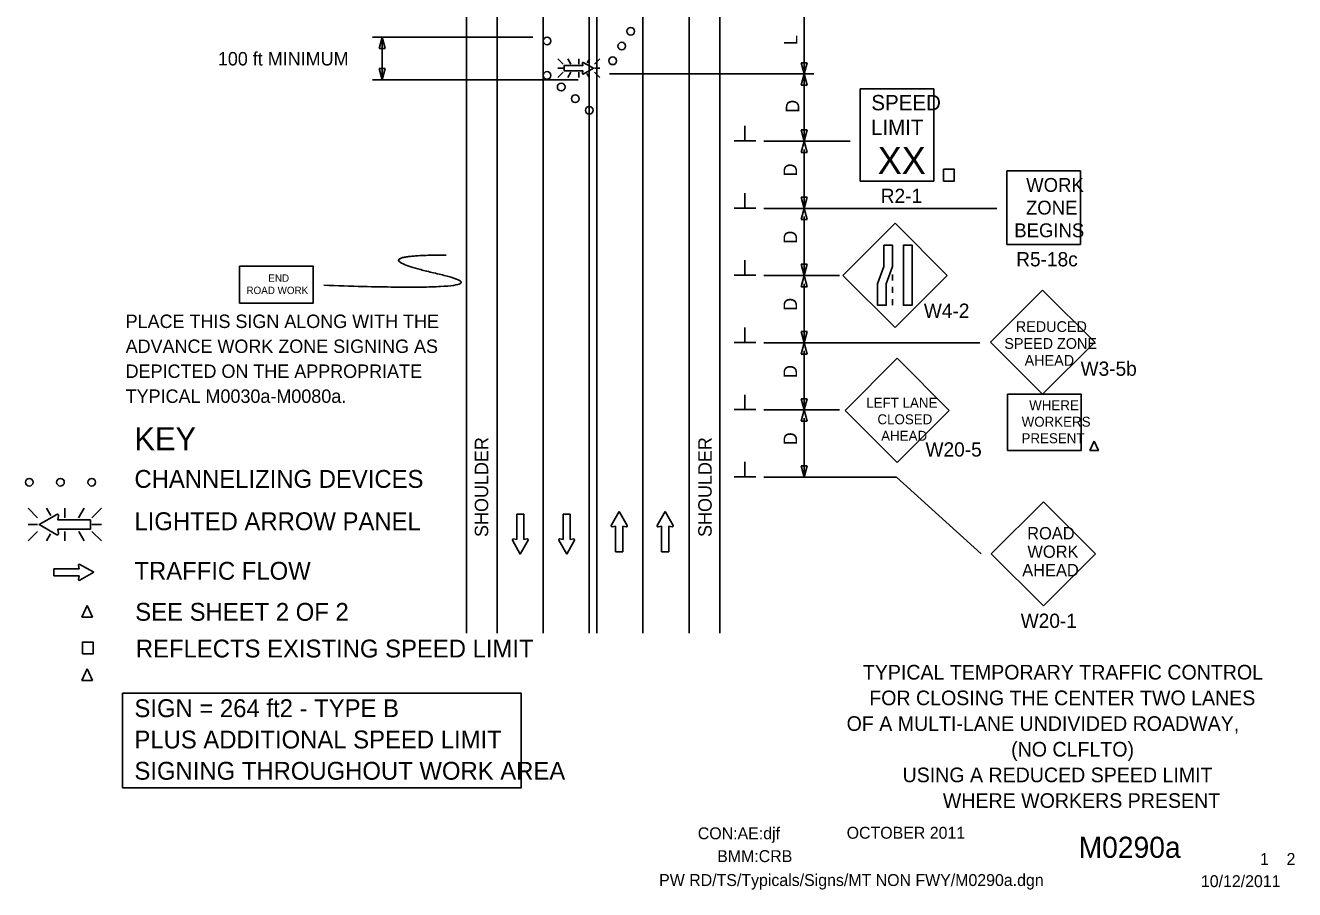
# Model space of a CAD drawing. Extents: x 16729 to 18475, y 5932 to 6920.
# Drawn here: x 16740 to 17402, y 5932 to 6382 of the extents above; entities that cross this region are included whole.
import ezdxf

# ---------------------------------------------------------------- set-up
doc = ezdxf.new("R2010")
doc.units = 0
for name, color, linetype in [('ALI_LEGAL_EX', 7, 'Continuous'), ('BORDER_SIGNAL_WO', 7, 'Continuous'), ('Level 44', 7, 'Continuous'), ('MT_SCRATCH_LEVEL_E', 7, 'Continuous'), ('PAVT_EDGE_EX', 7, 'Continuous'), ('TRAFFIC_SIGNS_PR', 7, 'Continuous'), ('TYPICAL_TEXT_DIMEN_EX', 7, 'Continuous'), ('TYPICAL_TEXT_DIMEN_PR', 7, 'Continuous')]:
    doc.layers.add(name, color=color, linetype=linetype)

msp = doc.modelspace()

# ---------------------------------------------------------------- linework, layer by layer
at = {"layer": 'ALI_LEGAL_EX'}
for p, q in [((17010.12, 6916.46), (17010.12, 6065.34)), ((17062.12, 6916.46), (17062.12, 6065.34))]:
    msp.add_line(p, q, dxfattribs=at)
for points in [[(17010.12, 6316.46), (17010.12, 6291.46)], [(17062.12, 6316.46), (17062.12, 6291.46)], [(17010.12, 6216.46), (17010.12, 6191.46)], [(17062.12, 6216.46), (17062.12, 6191.46)], [(17010.12, 6116.46), (17010.12, 6091.46)], [(17062.12, 6116.46), (17062.12, 6091.46)]]:
    msp.add_lwpolyline(points, dxfattribs=at)
at = {"layer": 'MT_SCRATCH_LEVEL_E'}
for p, q in [((17000.04, 6127.4), (16996.3, 6127.4)), ((16996.3, 6127.4), (16996.3, 6114.15)), ((17000.04, 6127.4), (16996.3, 6127.4)), ((16996.3, 6127.4), (16996.3, 6114.15)), ((17000.04, 6114.15), (17000.04, 6127.4)), ((17000.04, 6114.15), (17000.04, 6127.4)), ((17024.22, 6127.4), (17020.48, 6127.4)), ((17020.48, 6127.4), (17020.48, 6114.15)), ((17024.22, 6127.4), (17020.48, 6127.4)), ((17020.48, 6127.4), (17020.48, 6114.15)), ((17024.22, 6114.15), (17024.22, 6127.4)), ((17024.22, 6114.15), (17024.22, 6127.4)), ((17049.71, 6128.69), (17045.6, 6121.45)), ((17049.71, 6128.69), (17045.6, 6121.45)), ((17053.86, 6121.45), (17049.71, 6128.69)), ((17053.86, 6121.45), (17049.71, 6128.69)), ((17073.64, 6128.69), (17069.53, 6121.45)), ((17073.64, 6128.69), (17069.53, 6121.45)), ((17077.78, 6121.45), (17073.64, 6128.69)), ((17077.78, 6121.45), (17073.64, 6128.69)), ((17046.08, 6120.77), (17047.86, 6121.08)), ((17046.08, 6120.77), (17047.86, 6121.08)), ((17047.86, 6121.08), (17047.86, 6107.82)), ((17047.86, 6121.08), (17047.86, 6107.82)), ((17051.6, 6107.82), (17051.6, 6121.08)), ((17051.6, 6121.08), (17053.38, 6120.77)), ((17051.6, 6107.82), (17051.6, 6121.08)), ((17051.6, 6121.08), (17053.38, 6120.77)), ((17070.01, 6120.77), (17071.79, 6121.08)), ((17070.01, 6120.77), (17071.79, 6121.08)), ((17071.79, 6121.08), (17071.79, 6107.82)), ((17071.79, 6121.08), (17071.79, 6107.82)), ((17075.53, 6107.82), (17075.53, 6121.08)), ((17075.53, 6121.08), (17077.3, 6120.77)), ((17075.53, 6107.82), (17075.53, 6121.08)), ((17075.53, 6121.08), (17077.3, 6120.77)), ((16994.04, 6113.78), (16998.19, 6106.54)), ((16994.04, 6113.78), (16998.19, 6106.54)), ((16996.3, 6114.15), (16994.52, 6114.46)), ((16996.3, 6114.15), (16994.52, 6114.46)), ((16998.19, 6106.54), (17002.3, 6113.78)), ((16998.19, 6106.54), (17002.3, 6113.78)), ((17001.82, 6114.46), (17000.04, 6114.15)), ((17001.82, 6114.46), (17000.04, 6114.15)), ((17018.22, 6113.78), (17022.37, 6106.54)), ((17018.22, 6113.78), (17022.37, 6106.54)), ((17020.48, 6114.15), (17018.7, 6114.46)), ((17020.48, 6114.15), (17018.7, 6114.46)), ((17022.37, 6106.54), (17026.48, 6113.78)), ((17022.37, 6106.54), (17026.48, 6113.78)), ((17026, 6114.46), (17024.22, 6114.15)), ((17026, 6114.46), (17024.22, 6114.15)), ((17047.86, 6107.82), (17051.6, 6107.82)), ((17047.86, 6107.82), (17051.6, 6107.82)), ((17071.79, 6107.82), (17075.53, 6107.82)), ((17071.79, 6107.82), (17075.53, 6107.82)), ((16767.91, 6100.73), (16768.23, 6098.95)), ((16767.91, 6100.73), (16768.23, 6098.95)), ((16775.84, 6097.1), (16768.6, 6101.21)), ((16775.84, 6097.1), (16768.6, 6101.21)), ((16768.23, 6098.95), (16754.97, 6098.95)), ((16754.97, 6098.95), (16754.97, 6095.21)), ((16768.23, 6098.95), (16754.97, 6098.95)), ((16754.97, 6098.95), (16754.97, 6095.21)), ((16754.97, 6095.21), (16768.23, 6095.21)), ((16754.97, 6095.21), (16768.23, 6095.21)), ((16768.23, 6095.21), (16767.91, 6093.43)), ((16768.23, 6095.21), (16767.91, 6093.43)), ((16768.6, 6092.95), (16775.84, 6097.1)), ((16768.6, 6092.95), (16775.84, 6097.1))]:
    msp.add_line(p, q, dxfattribs=at)
for centre, start, end in [((17046.01, 6121.23), 150.42484, 279.96381), ((17046.01, 6121.23), 150.42484, 279.96381), ((17053.45, 6121.23), 260.03619, 29.77312), ((17053.45, 6121.23), 260.03619, 29.77312), ((17069.93, 6121.23), 150.42484, 279.96381), ((17069.93, 6121.23), 150.42484, 279.96381), ((17077.37, 6121.23), 260.03619, 29.77312), ((17077.37, 6121.23), 260.03619, 29.77312), ((16994.45, 6114), 80.03619, 209.77312), ((16994.45, 6114), 80.03619, 209.77312), ((17001.89, 6114), 330.42484, 99.96381), ((17001.89, 6114), 330.42484, 99.96381), ((17018.63, 6114), 80.03619, 209.77312), ((17018.63, 6114), 80.03619, 209.77312), ((17026.07, 6114), 330.42484, 99.96381), ((17026.07, 6114), 330.42484, 99.96381), ((16768.37, 6100.8), 60.42484, 189.96381), ((16768.37, 6100.8), 60.42484, 189.96381), ((16768.37, 6093.36), 170.03619, 299.77312), ((16768.37, 6093.36), 170.03619, 299.77312)]:
    msp.add_arc(centre, 0.463, start, end, dxfattribs=at)
at = {"layer": 'PAVT_EDGE_EX'}
for p, q in [((16970.12, 6916.46), (16970.12, 6065.34)), ((16986.12, 6916.46), (16986.12, 6065.34)), ((17086.12, 6916.46), (17086.12, 6065.34)), ((17102.12, 6916.46), (17102.12, 6065.34)), ((17034.12, 6439.88), (17034.12, 6065.34)), ((17038.12, 6439.88), (17038.12, 6065.34))]:
    msp.add_line(p, q, dxfattribs=at)
at = {"layer": 'TRAFFIC_SIGNS_PR'}
for p, q in [((17020.6, 6361.69), (17017.78, 6364.51)), ((17022.9, 6364.51), (17024.53, 6361.69)), ((17028.69, 6361.69), (17028.69, 6364.51)), ((17034.16, 6364.51), (17032.95, 6362.42)), ((17039.59, 6364.51), (17036.77, 6361.69)), ((17020.6, 6359.66), (17017.78, 6359.66)), ((17020.6, 6357.63), (17017.78, 6354.81)), ((17024.55, 6357.63), (17022.92, 6354.81)), ((17028.69, 6357.63), (17028.69, 6354.81)), ((17036.77, 6359.66), (17039.59, 6359.66)), ((17039.59, 6354.81), (17036.77, 6357.63)), ((17032.87, 6356.99), (17034.13, 6354.81)), ((17175.37, 6348.87), (17213.77, 6348.87)), ((17175.37, 6300.87), (17175.37, 6348.87)), ((17213.77, 6300.87), (17213.77, 6348.87)), ((17251.85, 6267.89), (17251.85, 6306.29)), ((17251.85, 6306.29), (17290.25, 6306.29)), ((17290.25, 6267.89), (17290.25, 6306.29)), ((17175.37, 6300.87), (17213.77, 6300.87)), ((17193.49, 6278.91), (17166.33, 6251.75)), ((17220.64, 6251.75), (17193.49, 6278.91)), ((17251.85, 6267.89), (17290.25, 6267.89)), ((17166.33, 6251.75), (17193.49, 6224.6)), ((17192.24, 6252.24), (17192.24, 6249.04)), ((17193.49, 6224.6), (17220.64, 6251.75)), ((17192.24, 6245.84), (17192.24, 6242.64)), ((17192.24, 6239.44), (17192.24, 6236.24)), ((17270.42, 6244.13), (17243.26, 6216.98)), ((17297.57, 6216.98), (17270.42, 6244.13)), ((17243.26, 6216.98), (17270.42, 6189.82)), ((17270.42, 6189.82), (17297.57, 6216.98)), ((17194.61, 6208.56), (17167.46, 6181.4)), ((17221.77, 6181.4), (17194.61, 6208.56)), ((17252.1, 6189.85), (17290.5, 6189.85)), ((17252.1, 6160.53), (17252.1, 6189.85)), ((17290.5, 6160.53), (17290.5, 6189.85)), ((17167.46, 6181.4), (17194.61, 6154.25)), ((17194.61, 6154.25), (17221.77, 6181.4)), ((17252.1, 6160.53), (17290.5, 6160.53)), ((17270.83, 6133.88), (17243.68, 6106.73)), ((17297.99, 6106.73), (17270.83, 6133.88)), ((16741.65, 6130.48), (16746.58, 6125.55)), ((16753.41, 6126.66), (16751.2, 6130.49)), ((16760.73, 6125.55), (16760.73, 6130.49)), ((16767.97, 6125.55), (16770.82, 6130.49)), ((16774.88, 6125.55), (16779.82, 6130.49)), ((16746.58, 6122), (16741.65, 6122)), ((16774.88, 6122), (16779.82, 6122)), ((16741.65, 6113.51), (16746.58, 6118.44)), ((16751.16, 6113.51), (16753.27, 6117.17)), ((16760.73, 6118.44), (16760.73, 6113.51)), ((16770.86, 6113.51), (16768.01, 6118.44)), ((16774.88, 6118.44), (16779.82, 6113.5)), ((17243.68, 6106.73), (17270.83, 6079.57)), ((17270.83, 6079.57), (17297.99, 6106.73))]:
    msp.add_line(p, q, dxfattribs=at)
for points in [[(17030.51, 6362.34), (17030.74, 6361.05), (17021.02, 6361.05), (17021.02, 6358.3), (17030.74, 6358.3), (17030.51, 6357)], [(17031.01, 6356.64), (17036.32, 6359.66), (17031.01, 6362.7)], [(17297.25, 6165.47), (17295.02, 6160.53)], [(17295.02, 6160.53), (17297.25, 6165.47)], [(17295.02, 6160.53), (17299.49, 6160.53)], [(17299.49, 6160.53), (17295.02, 6160.53)], [(17299.49, 6160.53), (17297.25, 6165.47)], [(17297.25, 6165.47), (17299.49, 6160.53)], [(16756.66, 6127.27), (16747.37, 6122), (16756.66, 6116.67)], [(16757.53, 6117.3), (16757.13, 6119.57), (16774.15, 6119.57), (16774.15, 6124.37), (16757.13, 6124.37), (16757.54, 6126.65)], [(16772.39, 6079.87), (16769.59, 6073.7)], [(16775.19, 6073.7), (16772.39, 6079.87)], [(16769.59, 6073.7), (16775.19, 6073.7)], [(16769.59, 6040.7), (16772.39, 6046.87)], [(16772.39, 6046.87), (16775.19, 6040.7)], [(16775.19, 6040.7), (16769.59, 6040.7)]]:
    msp.add_lwpolyline(points, dxfattribs=at)
for points in [[(17218.79, 6300.87), (17224.38, 6300.87), (17224.38, 6307.04), (17218.79, 6307.04)], [(17192.24, 6267.49), (17192.24, 6256.31), (17188.89, 6247.43), (17188.89, 6236.24), (17184.4, 6236.24), (17184.4, 6247.43), (17187.74, 6256.31), (17187.74, 6267.49)], [(17202.37, 6267.49), (17202.37, 6236.24), (17197.88, 6236.24), (17197.88, 6267.49)], [(16851.85, 6237.29), (16890.25, 6237.29), (16890.25, 6256.49), (16851.85, 6256.49)], [(16769.91, 6054.58), (16775.5, 6054.58), (16775.5, 6060.75), (16769.91, 6060.75)]]:
    msp.add_lwpolyline(points, close=True, dxfattribs=at)
for centre in [(17055.74, 6378.87), (17012.15, 6373.87), (17051.04, 6371.19), (17046.34, 6363.52), (17012.15, 6355.91), (17019.48, 6349.85), (17026.8, 6343.78), (17034.13, 6337.72), (16742.21, 6144.03), (16758.51, 6144.03), (16774.81, 6144.03)]:
    msp.add_circle(centre, 2, dxfattribs=at)
for centre, radius, start, end in [((17030.85, 6362.4), 0.341, 61.48329, 189.95933), ((17030.85, 6356.94), 0.341, 170.73078, 298.89165), ((16756.95, 6126.75), 0.598, 350.73078, 118.89165), ((16756.95, 6117.2), 0.597, 241.48329, 9.95933)]:
    msp.add_arc(centre, radius, start, end, dxfattribs=at)
msp.add_open_spline([(16959.57, 6262.32), (16912.34, 6262.32), (16997.36, 6242.97), (16895.79, 6246.61)], degree=2, dxfattribs=at)
at = {"layer": 'TYPICAL_TEXT_DIMEN_EX'}
msp.add_lwpolyline([(16790.87, 6034.08), (16998.68, 6034.08), (16998.68, 5984.89), (16790.87, 5984.89)], close=True, dxfattribs=at)
at = {"layer": 'TYPICAL_TEXT_DIMEN_PR'}
for p, q in [((17146.12, 6388.9), (17146.12, 6356.65)), ((16921.12, 6375.88), (17004.78, 6375.88)), ((16924.55, 6370.01), (16926.12, 6375.88)), ((16926.12, 6375.88), (16926.12, 6353.68)), ((16926.12, 6375.88), (16927.69, 6370.01)), ((16926.12, 6370.01), (16924.55, 6370.01)), ((16927.69, 6370.01), (16926.12, 6370.01)), ((16926.12, 6353.68), (16924.55, 6359.55)), ((16924.55, 6359.55), (16926.12, 6359.55)), ((16926.12, 6359.55), (16927.69, 6359.55)), ((16927.69, 6359.55), (16926.12, 6353.68)), ((17146.12, 6356.65), (17144.55, 6362.51)), ((17144.55, 6362.51), (17146.12, 6362.51)), ((17146.12, 6362.51), (17147.69, 6362.51)), ((17147.69, 6362.51), (17146.12, 6356.65)), ((16921.12, 6353.68), (17028.42, 6353.68)), ((17044.68, 6356.65), (17151.12, 6356.65)), ((17144.55, 6350.79), (17146.12, 6356.65)), ((17146.12, 6356.65), (17146.12, 6321.65)), ((17146.12, 6356.65), (17147.69, 6350.79)), ((17146.12, 6350.79), (17144.55, 6350.79)), ((17147.69, 6350.79), (17146.12, 6350.79)), ((17115.24, 6321.82), (17115.24, 6329.61)), ((17146.12, 6321.65), (17144.55, 6327.51)), ((17144.55, 6327.51), (17146.12, 6327.51)), ((17146.12, 6327.51), (17147.69, 6327.51)), ((17147.69, 6327.51), (17146.12, 6321.65)), ((17120.87, 6321.82), (17109.62, 6321.82)), ((17125.12, 6321.65), (17170.03, 6321.65)), ((17144.55, 6315.79), (17146.12, 6321.65)), ((17146.12, 6321.65), (17147.69, 6315.79)), ((17146.12, 6315.79), (17144.55, 6315.79)), ((17146.12, 6317.39), (17146.12, 6286.65)), ((17147.69, 6315.79), (17146.12, 6315.79)), ((17115.24, 6286.82), (17115.24, 6294.61)), ((17146.12, 6286.65), (17144.55, 6292.51)), ((17144.55, 6292.51), (17146.12, 6292.51)), ((17146.12, 6292.51), (17147.69, 6292.51)), ((17147.69, 6292.51), (17146.12, 6286.65)), ((17120.87, 6286.82), (17109.62, 6286.82)), ((17125.12, 6286.65), (17246.53, 6286.65)), ((17144.55, 6280.79), (17146.12, 6286.65)), ((17146.12, 6286.65), (17147.69, 6280.79)), ((17146.12, 6280.79), (17144.55, 6280.79)), ((17146.12, 6282.39), (17146.12, 6251.65)), ((17147.69, 6280.79), (17146.12, 6280.79)), ((17115.24, 6251.82), (17115.24, 6259.61)), ((17120.87, 6251.82), (17109.62, 6251.82)), ((17146.12, 6251.65), (17144.55, 6257.51)), ((17144.55, 6257.51), (17146.12, 6257.51)), ((17146.12, 6257.51), (17147.69, 6257.51)), ((17147.69, 6257.51), (17146.12, 6251.65)), ((17125.12, 6251.65), (17164.54, 6251.65)), ((17144.55, 6245.79), (17146.12, 6251.65)), ((17146.12, 6245.79), (17144.55, 6245.79)), ((17146.12, 6251.65), (17147.69, 6245.79)), ((17146.12, 6247.39), (17146.12, 6216.65)), ((17147.69, 6245.79), (17146.12, 6245.79)), ((17115.24, 6216.82), (17115.24, 6224.61)), ((17146.12, 6216.65), (17144.55, 6222.51)), ((17144.55, 6222.51), (17146.12, 6222.51)), ((17146.12, 6222.51), (17147.69, 6222.51)), ((17147.69, 6222.51), (17146.12, 6216.65)), ((17120.87, 6216.82), (17109.62, 6216.82)), ((17125.12, 6216.65), (17237.67, 6216.65)), ((17144.55, 6210.79), (17146.12, 6216.65)), ((17146.12, 6216.65), (17147.69, 6210.79)), ((17146.12, 6212.39), (17146.12, 6181.65)), ((17146.12, 6210.79), (17144.55, 6210.79)), ((17147.69, 6210.79), (17146.12, 6210.79)), ((17115.24, 6181.82), (17115.24, 6189.61)), ((17146.12, 6181.65), (17144.55, 6187.51)), ((17144.55, 6187.51), (17146.12, 6187.51)), ((17146.12, 6187.51), (17147.69, 6187.51)), ((17147.69, 6187.51), (17146.12, 6181.65)), ((17120.87, 6181.82), (17109.62, 6181.82)), ((17125.12, 6181.65), (17164.54, 6181.65)), ((17144.55, 6175.79), (17146.12, 6181.65)), ((17146.12, 6181.65), (17147.69, 6175.79)), ((17146.12, 6175.79), (17144.55, 6175.79)), ((17146.12, 6177.39), (17146.12, 6146.65)), ((17147.69, 6175.79), (17146.12, 6175.79)), ((17115.24, 6146.82), (17115.24, 6154.61)), ((17146.12, 6146.65), (17144.55, 6152.51)), ((17144.55, 6152.51), (17146.12, 6152.51)), ((17146.12, 6152.51), (17147.69, 6152.51)), ((17147.69, 6152.51), (17146.12, 6146.65)), ((17120.87, 6146.82), (17109.62, 6146.82)), ((17125.12, 6146.65), (17194.29, 6146.65)), ((17194.29, 6146.65), (17238.34, 6106.72))]:
    msp.add_line(p, q, dxfattribs=at)

# ---------------------------------------------------------------- texts
at = {"layer": 'BORDER_SIGNAL_WO'}
for s, height, p in [('CON:AE:djf', 6.2, (17090.69, 5958.06)), ('    OCTOBER 2011    ', 6.2, (17159.08, 5958.34)), ('    M0290a   ', 11, (17272.86, 5948.38)), ('BMM:CRB   ', 6.2, (17100.81, 5946.17)), (' 1    2 ', 6.2, (17381.45, 5944.7)), ('PW RD/TS/Typicals/Signs/MT NON FWY/M0290a.dgn    ', 6.2, (17070.55, 5933.71)), ('10/12/2011    ', 6.2, (17352.93, 5933.13))]:
    msp.add_text(s, height=height, dxfattribs=at).set_placement(p)
at = {"layer": 'Level 44'}
for s, p in [('TYPICAL TEMPORARY TRAFFIC CONTROL', (17176.72, 6041.25)), ('FOR CLOSING THE CENTER TWO LANES', (17180.06, 6027.88)), ('OF A MULTI-LANE UNDIVIDED ROADWAY, ', (17168.26, 6014.51)), ('(NO CLFLTO)', (17254.01, 6001.14)), ('USING A REDUCED SPEED LIMIT', (17197.43, 5987.77)), ('WHERE WORKERS PRESENT', (17218.43, 5974.4))]:
    msp.add_text(s, height=7.6293, dxfattribs=at).set_placement(p)
at = {"layer": 'TRAFFIC_SIGNS_PR'}
for s, height, p in [('SPEED', 8, (17181.14, 6337.73)), ('LIMIT', 8, (17180.98, 6324.93)), ('XX', 14.031, (17184.49, 6304.63)), ('WORK', 7.217, (17261.85, 6295.25)), ('R2-1', 7.44, (17186.05, 6289.43)), ('ZONE', 7.217, (17261.73, 6283.44)), ('BEGINS', 7.217, (17255.66, 6271.63)), ('R5-18c', 7.44, (17256.66, 6256.45)), ('END', 3.831, (16866.85, 6248.42)), ('ROAD WORK', 3.831, (16855.46, 6242.04)), ('W4-2', 7.44, (17208.51, 6229.62)), ('PLACE THIS SIGN ALONG WITH THE', 7, (16792.47, 6224.34)), ('REDUCED', 5.6, (17256.47, 6222.28)), ('SPEED ZONE', 5.6, (17250.47, 6213.48)), ('ADVANCE WORK ZONE SIGNING AS', 7, (16792.47, 6211.34)), ('DEPICTED ON THE APPROPRIATE', 7, (16792.47, 6198.34)), ('AHEAD', 5.6, (17261.03, 6204.68)), ('W3-5b', 7.44, (17290.21, 6199.44)), ('TYPICAL M0030a-M0080a.', 7, (16792.47, 6185.34)), ('LEFT LANE', 5.2, (17178.49, 6182.8)), ('WHERE', 5.2, (17263.41, 6181.53)), ('CLOSED', 5.2, (17184.33, 6174.2)), ('WORKERS', 5.2, (17259.49, 6172.93)), ('AHEAD', 5.2, (17186.27, 6165.6)), ('PRESENT', 5.2, (17259.42, 6164.33)), ('W20-5', 7.44, (17209.38, 6157.37)), ('ROAD', 6.4, (17262.37, 6114.26)), ('WORK', 6.4, (17262.48, 6104.66)), ('AHEAD', 6.4, (17259.79, 6095.06)), ('W20-1', 7.44, (17259, 6068.13))]:
    msp.add_text(s, height=height, dxfattribs=at).set_placement(p)
at = {"layer": 'TYPICAL_TEXT_DIMEN_EX'}
for s, height, p in [('KEY', 12, (16797.05, 6160.65)), ('CHANNELIZING DEVICES', 9.3, (16797.05, 6141.09)), ('LIGHTED ARROW PANEL', 9.3, (16797.05, 6119.04)), ('TRAFFIC FLOW', 9.3, (16797.05, 6093.24)), ('SEE SHEET 2 OF 2', 9.3, (16797.48, 6071.86)), ('REFLECTS EXISTING SPEED LIMIT', 9.3, (16797.79, 6052.74)), ('SIGN = 264 ft2 - TYPE B', 9.3, (16797.05, 6021.67)), ('PLUS ADDITIONAL SPEED LIMIT', 9.3, (16797.05, 6005.37)), ('SIGNING THROUGHOUT WORK AREA', 9.3, (16797.05, 5989.07))]:
    msp.add_text(s, height=height, dxfattribs=at).set_placement(p)
at = {"layer": 'TYPICAL_TEXT_DIMEN_PR'}
for s, p in [('L', (17142.66, 6371.71)), ('D', (17143.56, 6336.43)), ('D', (17142.39, 6303.27)), ('D', (17142.39, 6268.27)), ('D', (17142.39, 6233.27)), ('D', (17142.39, 6198.27)), ('SHOULDER', (16981.44, 6115.5)), ('SHOULDER', (17097.93, 6115.5)), ('D', (17142.39, 6163.27))]:
    msp.add_text(s, height=7, rotation=90, dxfattribs=at).set_placement(p)
msp.add_text('100 ft MINIMUM', height=7, dxfattribs=at).set_placement((16840.53, 6361.09))

doc.saveas('drawing.dxf')
